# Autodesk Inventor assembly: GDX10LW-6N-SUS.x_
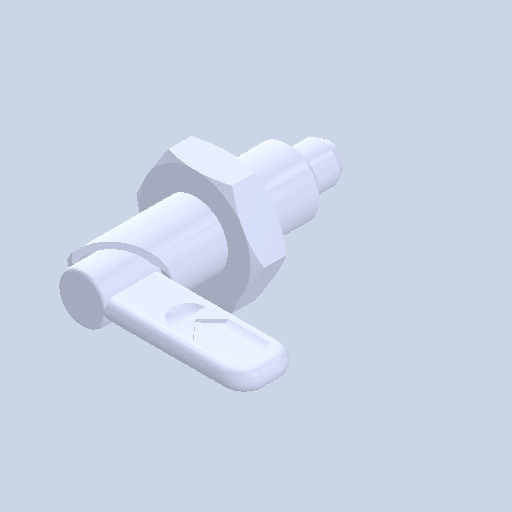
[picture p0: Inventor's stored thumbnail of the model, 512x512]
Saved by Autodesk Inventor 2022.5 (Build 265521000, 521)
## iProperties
Created: 2024-06
Part Number: GDX10LW-6N-SUS.x_
Document SubType Name: Assembly
Designer: ImaoCorp
Author: ImaoCorp
Sending System: SOLIDWORKS 2022-2022290
MC: AMD64
MC_MODEL: Intel64 Family 6 Model 60 Stepping 3, GenuineIntel
OS: Windows_NT
FRU: Parasolid Version 33.1, build 260,  4-25-2022
FORMAT: text
GUISE: transmit
KEY: FILEGDX10LW-6N-SUS.x_t
DATE: Wed Jun 12 09:31:37 2024
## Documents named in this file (4)
- Y:\5.更新分\2024年対応\xxxx_GDX\データ_imao品番\gdx10lw-6n-sus\GDX10LW-6N-SUS.x_.iam
- Y:\5.更新分\2024年対応\xxxx_GDX\データ_imao品番\gdx10lw-6n-sus\GDX10LW-6N-SUS_01.ipt
- Y:\5.更新分\2024年対応\xxxx_GDX\データ_imao品番\gdx10lw-6n-sus\GDX10LW-6N-SUS_02.ipt
- Y:\5.更新分\2024年対応\xxxx_GDX\データ_imao品番\gdx10lw-6n-sus\GDX10LW-6N-SUS_03.ipt
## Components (3 placed, 3 different names)
1. GDX10LW-6N-SUS_01
2. GDX10LW-6N-SUS_02
3. GDX10LW-6N-SUS_03
